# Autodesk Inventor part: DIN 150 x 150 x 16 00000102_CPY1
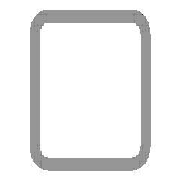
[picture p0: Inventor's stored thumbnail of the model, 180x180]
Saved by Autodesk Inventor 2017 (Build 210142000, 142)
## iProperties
Created: 2017-11
Part Number: DIN 150 x 150 x 16 00000102_CPY1
Material: Steel, Mild
Description: Cold formed welded structural hollow sections of non-alloy and fine grain structural steel
Document SubType Name: Modeling
Standard: DIN
Designer: iusti
Standard Revision: 2006-07
Standards Organization: DIN
Language: en-US
Size Designation: 150 x 150 x 16
Categories: <MemberInstance><Categories><Category DisplayName="Structural Shapes" InternalName="089c4875-fa83-4c05-b084-43b9cc11f5ed" Mnemonic="GRDR"><CategoryParameter Dis
Stock Number: 150 x 150 x 16
Mass: 90369.3 g
Surface Area: 14539.6 cm^2
Volume: 11512 cm^3
Density: 7.85 g/cm^3
Appearance: Semi-Polished
IsCustomPart: 1
G_W: 150.000 mm
G_H: 150.000 mm
G_L: 1539.608 mm
+A2D54500-A6BB-4D6E-934F-4456235B9375+CUTDETAIL2: Cut
_CCFamilyMember: 76
_CCFamilyDisplayName: DIN EN 10219-2 (Square Hollow Section - Cold Formed) - Cold formed welded structural hollow sections of non-alloy and fine grain structural steel
_FrameMemberDoc: Frame Member File
_Version: 15.0.0
_GetPNFromCC: 1
Author: iusti
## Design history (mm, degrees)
node "Start plane"
node "End plane"
sketch "Sketch"
  geometry: L1 (-75, -27)-(-75, 27); L2 (-27, 75)-(27, 75); L3 (75, 27)-(75, -27); L4 (27, -75)-(-27, -75); L5 (-27, 59)-(27, 59); L6 (59, 27)-(59, -27); L7 (27, -59)-(-27, -59); L8 (-59, -27)-(-59, 27); L9 (0, 118.918)-(0, -118.918) reference; L10 (-118.918, 0)-(118.918, 0) reference; A1 r 48 centre (-27, -27) between (-75, -27) and (-27, -75); A2 r 48 centre (-27, 27) between (-27, 75) and (-75, 27); A3 r 48 centre (27, 27) between (75, 27) and (27, 75); A4 r 48 centre (27, -27) between (27, -75) and (75, -27); A5 r 32 centre (-27, 27) between (-27, 59) and (-59, 27); A6 r 32 centre (27, 27) between (59, 27) and (27, 59); A7 r 32 centre (27, -27) between (27, -59) and (59, -27); A8 r 32 centre (-27, -27) between (-59, -27) and (-27, -59)
  constraints: 16 end point, 16 point on circle, 8 centre point, 8 tangent, 4 parallel, 3 equal radius, 2 perpendicular, 7 other
  dimensions: "d7" = 48 radius of A1 (= G_IR); "d10" = 150 distance between parallel lines of L2 L4 (= G_H); "d11" = 150 distance between parallel lines of L1 L3 (= G_W); "d12" = 16 distance between parallel lines of L3 L6 (= G_T); "d15" = 75 distance between parallel lines of L2 L10 (= 0.5 x d10); "d16" = 75 distance between parallel lines of L9 L3 (= 0.5 x d11)
extrude "Body" new body sketch "Sketch" stored distance "d3" = 1539.60835 (= G_L); taper "d4" = 0 deg
node "Driven Length"
  sketch "Sketch3"
    geometry: L1 (0, 0)-(10, 0) reference
    constraints: 2 end point, 1 horizontal
  workplane "Work Plane3"
  sketch "Sketch4"
    geometry: L1 (-2, 0)-(12, 0) reference; L2 (-2, 1539.608)-(12, 1539.608) reference
    dimensions: "d18" = 1539.60835 distance between parallel lines of L1 L2 (derived)
workplane "Work Plane5"
split "Split2"
body "Solid1"
other parameters: "G_W" = 150 [user parameter; used in 1 equation term], "G_H" = 150 [user parameter; used in 1 equation term], "G_T" = 16 [user parameter; used in 1 equation term], "G_IR" = 48 [user parameter; used in 1 equation term], "G_L" = 1539.60835 (= d18) [user parameter; used in 1 equation term], "G_OFFSET_START" = 0 [user parameter; used in 1 equation term], "G_OFFSET_END" = -75 [user parameter; used in 1 equation term], "d13" = 0 (computed from G_OFFSET_START), "d14" = 1539.60835 (= G_OFFSET_END + B_L), "B_L" = 1614.60835 [user parameter; used in 1 equation term], "d17" = 90 deg
